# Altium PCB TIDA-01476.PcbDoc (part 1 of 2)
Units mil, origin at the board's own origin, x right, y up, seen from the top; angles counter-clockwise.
Board outline 2952.76 x 1377.95 mil, 4 copper layers (Layer 1 - Top Layer, Layer 2 - GND, Layer 3 - PWR, Layer 4 - Bottom Layer), stack 32.668 mil thick; 140 components, 50 nets, 358 pads, 357 vias.
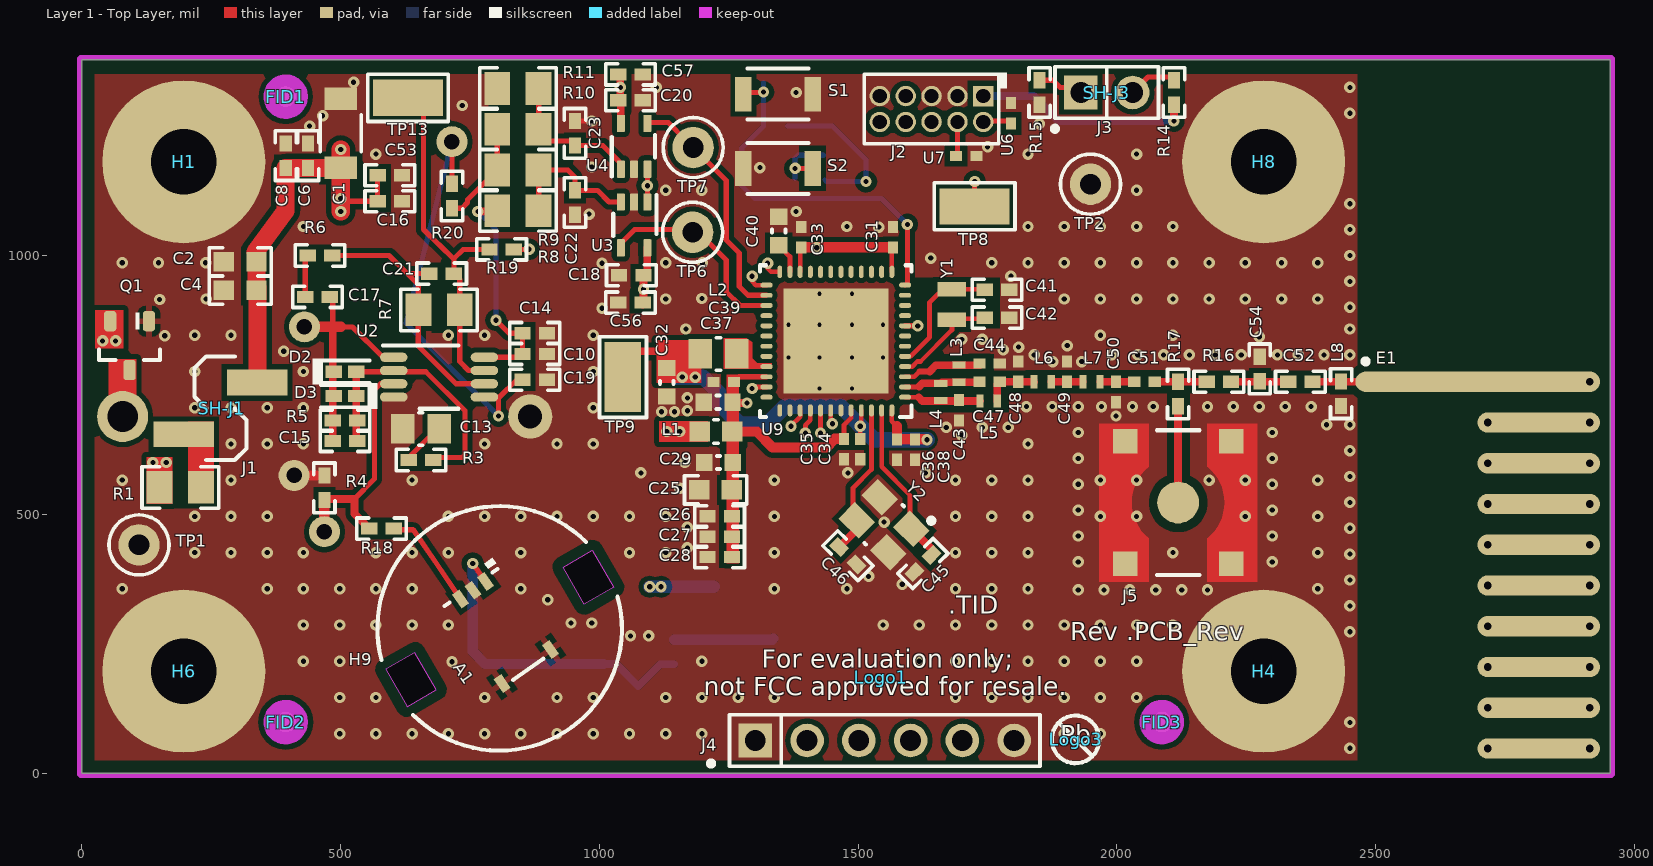
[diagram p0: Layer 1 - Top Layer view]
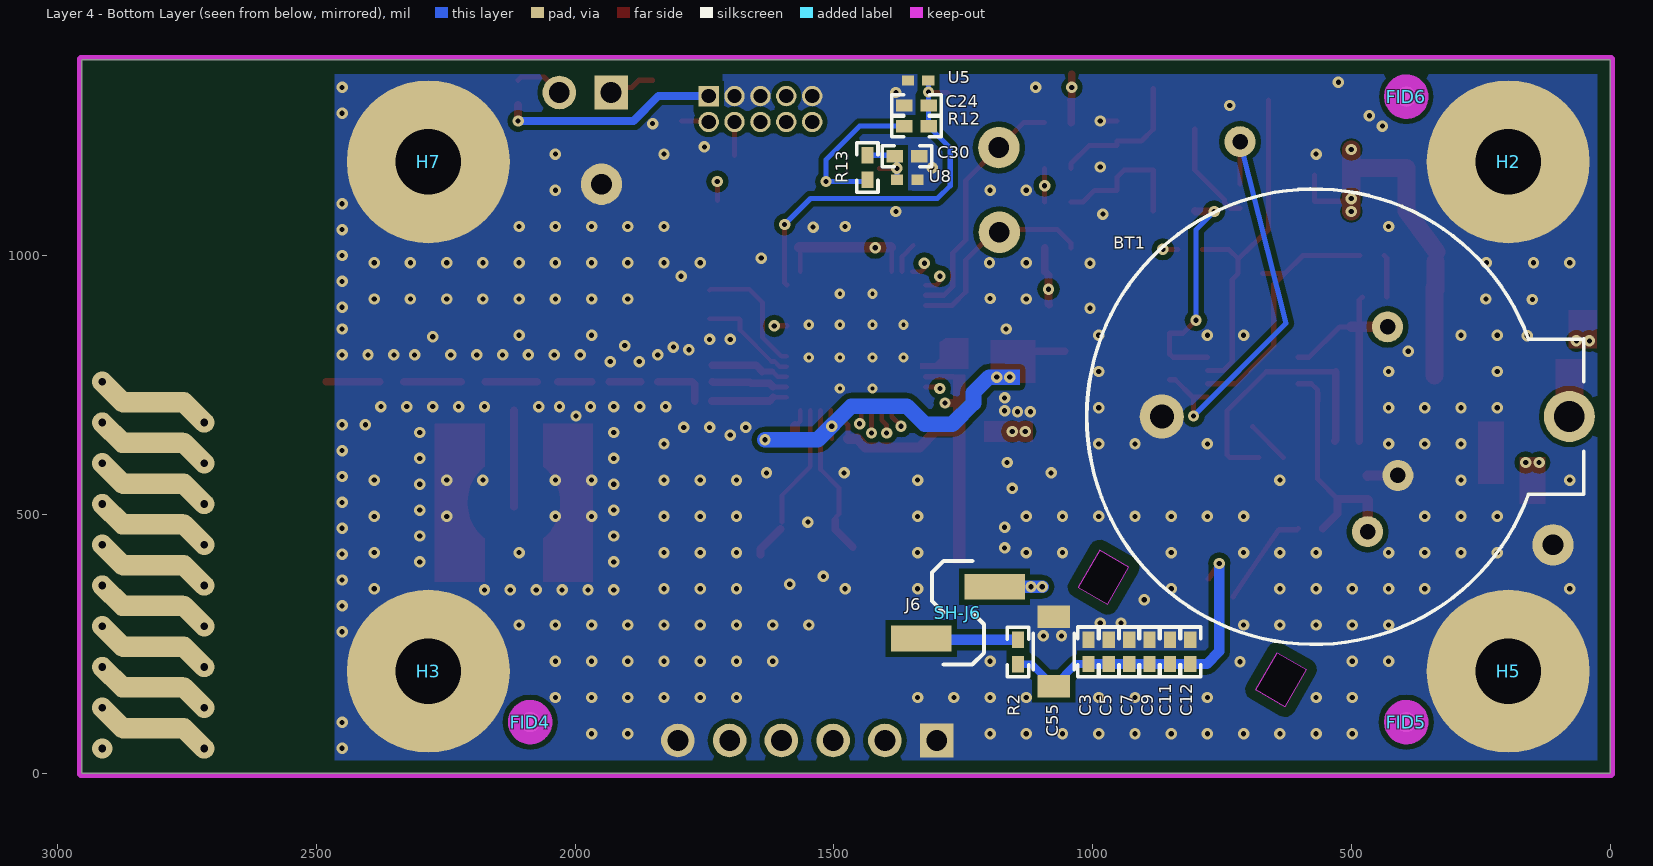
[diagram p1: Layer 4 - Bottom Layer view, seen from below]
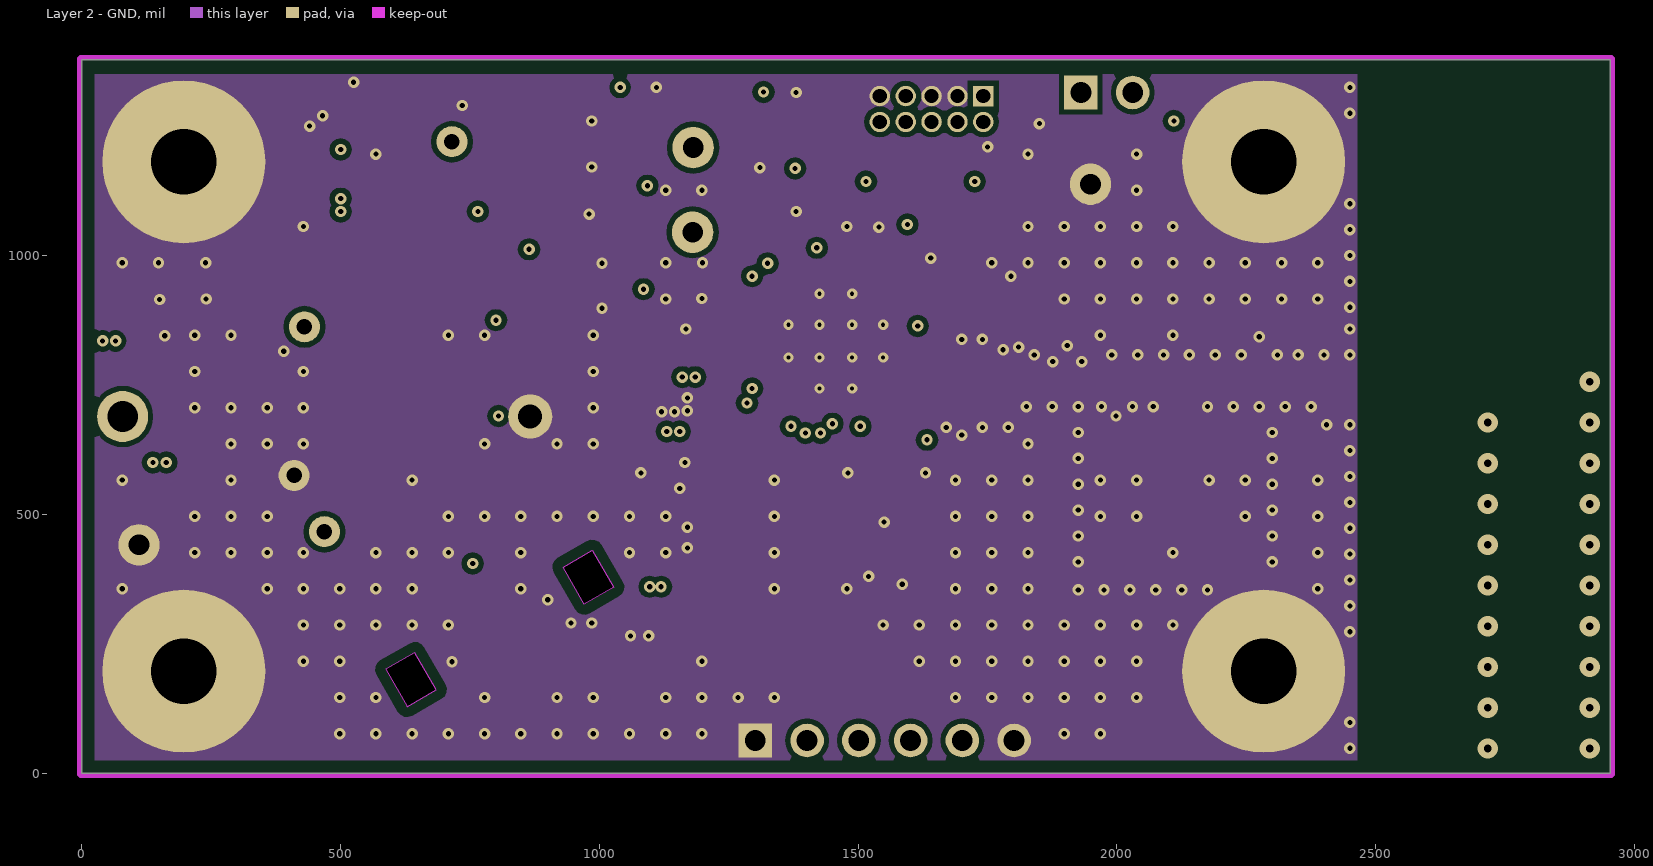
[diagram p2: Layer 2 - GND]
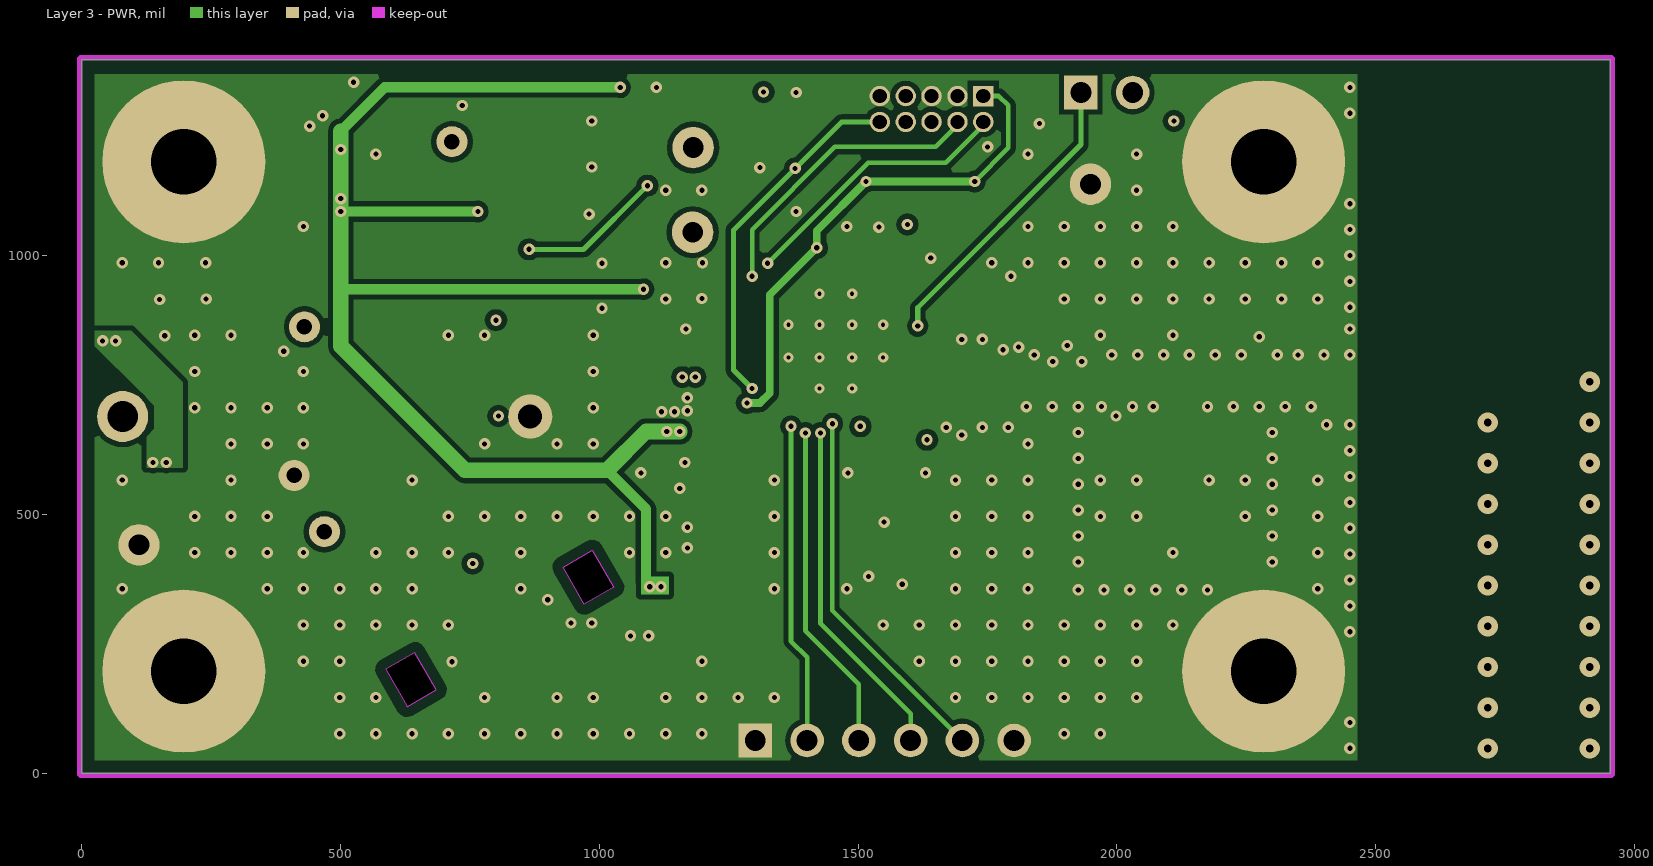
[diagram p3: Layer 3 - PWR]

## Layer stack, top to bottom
Top Solder: solder mask 0.4, Solder Resist, Dk 3.5
Layer 1 - Top Layer: signal copper 1.417
Dielectric1: core 9, 370HR, Dk 4.5
Layer 2 - GND: signal copper 1.417
Dielectric 3: prepreg 9, 370HR, Dk 4.5
Layer 3 - PWR: signal copper 1.417
Dielectric 2: core 9, 370HR, Dk 4.5
Layer 4 - Bottom Layer: signal copper 1.417
Bottom Solder: solder mask 0.4, Solder Resist, Dk 3.5

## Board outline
0,0 2952.76,0 2952.76,1377.95 0,1377.95

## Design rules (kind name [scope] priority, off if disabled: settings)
BoardOutlineClearance [All] p1: gap=20 ignorepadtopadclearanceinfootprint=FALSE
Clearance Clearance_1 [inpoly] p1: gap=10 ignorepadtopadclearanceinfootprint=FALSE except(0: Arc-Hole Track-Hole SMDPad-Hole THPad-Hole Via-Hole Fill-Hole Poly-Hole Region-Hole Text-Hole)
Clearance "Stitching GND" [IsStitchingVia and InNet('GND') vs (IsVia and (Not IsStitchingVia)) Or IsPad] p2: gap=20 ignorepadtopadclearanceinfootprint=FALSE except(0: Arc-Hole Track-Hole SMDPad-Hole THPad-Hole Via-Hole Fill-Hole Poly-Hole Region-Hole Text-Hole)
Clearance [All] p3: gap=5.91 ignorepadtopadclearanceinfootprint=FALSE except(0: Arc-Hole Track-Hole SMDPad-Hole THPad-Hole Via-Hole Fill-Hole Poly-Hole Region-Hole Text-Hole)
ComponentClearance ComponentClearance_Shunt [InComponentClass('Header') vs InComponentClass('Shunt')] p1: gap=0 collisioncheckmode=3 verticalgap=0 showdistances=FALSE
ComponentClearance ComponentClearance_H9 [incomponent('A1') vs incomponent('H9')] p2: gap=0 collisioncheckmode=3 verticalgap=0 showdistances=FALSE
ComponentClearance [All] p3: gap=3.94 collisioncheckmode=3 verticalgap=3.94 showdistances=FALSE
FabricationTestPointUsage TestPointUsage [All] p1: valid=0 allowmultiple=FALSE
FabricationTestpoint Testpoint [All] p1: side=3 testpointundercomponent=TRUE minsize=40 maxsize=100 preferedsize=60 minholesize=0 maxholesize=40 preferedholesize=32 testpointgrid=1 allowsidetop=TRUE allowsidebottom=TRUE usegrid=TRUE gridtolerance=0.01
HoleSize [All] p1: absolutevalues=TRUE maxlimit=500 minlimit=7.8 maxpercent=80.000 minpercent=20.000
MinimumAnnularRing [All] p1: minimumring=5
MinimumSolderMaskSliver [All] p1: minsoldermaskwidth=4
PolygonConnect PolygonConnect_TR [incomponent('A1') or  incomponent('Q1')] p1: connectstyle=Relief reliefconductorwidth=12 reliefentries=4 polygonreliefangle="90 Angle" airgapwidth=10
PolygonConnect [All] p2: connectstyle=Direct reliefconductorwidth=10 reliefentries=4 polygonreliefangle="90 Angle" airgapwidth=10
RoutingVias [All] p1: holewidth=10 width=22 viastyle="Through Hole" minholewidth=7.8 minwidth=19 maxholewidth=28 maxwidth=50
SilkToBoardRegionClearance [All] p1 off:
SilkToSilkClearance SilkToSilkClearance_1 [(HasFootprint('Pb-Free_Overlay_Medium') OR HasFootprint('Pb-Free_Overlay_Small')) vs (HasFootprint('Pb-Free_Overlay_Medium') OR HasFootprint('Pb-Free_Overlay_Small'))] p1: silktosilkclearance=0
SilkToSilkClearance [All] p2: silktosilkclearance=3
SilkToSolderMaskClearance SilkscreenOverComponentPads [IsPad] p1: minsilkscreentomaskgap=3 clearancetoexposedcopper=TRUE
SolderMaskExpansion [All] p1: expansion=0
Width [All] p1: maxlimit=100 minlimit=6 preferedwidth=10 minimp=50.000000 maximp=50.000000 favimp=50.000000
22 further rules are at their usual default settings.

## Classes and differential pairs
component class Shunt: SH-J1 SH-J3 SH-J6
component class AssemblyNote: ZZ1 ZZ2 ZZ3 ZZ4
component class TIDA-01476_POWER_PIR_802: A1 BT1 C1 C2 C3 C4 C5 C6 C7 C8 C9 C10 C11 C12 C13 C14 C15 C16 C17 C18 C19 C20 C21 C22 C23 C53 C55 C56 C57 D2 D3 J1 J6 Q1 R1 R2 R3 R4 R5 R6 R7 R8 R9 R10 R11 R18 R19 R20 TP1 TP2 TP6 TP7 TP13 U2 U3 U4
component class TIDA-01476_MCU: C24 C25 C26 C27 C28 C29 C30 C31 C32 C33 C34 C35 C36 C37 C38 C39 C40 C41 C42 C43 C44 C45 C46 C47 C48 C49 C50 C51 C52 C54 E1 J2 J3 J4 J5 L1 L2 L3 L4 L5 L6 L7 L8 R12 R13 R14 R15 R16 R17 S1 S2 TP8 TP9 U5 U6 U7 U8 U9 Y1 Y2
component class Header: J1 J2 J3 J4 J6
component class "Mounting Holes": H1 H4 H6 H8
component class TIDA-01476_TID_Hardware: FID1 FID2 FID3 FID4 FID5 FID6 H1 H2 H3 H4 H5 H6 H7 H8 H9 Logo1 Logo3 SH-J1 SH-J3 SH-J6 ZZ1 ZZ2 ZZ3 ZZ4
component class FiducialMark: FID1 FID2 FID3 FID4 FID5 FID6

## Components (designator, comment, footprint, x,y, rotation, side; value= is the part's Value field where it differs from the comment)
A1 "IRS-B210ST01-R1" Murata_IRS-B210ST01 807.09,279.53 r305 top value=3.6mVp-p
BT1 "BS-7" BAT_BS-7 472.44,688.98 r0 bottom locked
C1 "C3216X5R1A107M160AC" 1206_190 500,1236.22 r90 top value=100uF
C2 "C1608X5R0J106M" 0603 305.78,988.19 r180 top value=10uF
C3 "GRM155R60J106ME44D" 0402 1007.89,234.25 r90 bottom value=10uF
C4 "C1608X7R1C105K" 0603 305.78,933.07 r180 top value=1uF
C5 "C1005X5R1A105K050BB" 0402 968.52,234.25 r90 bottom value=1uF
C6 "C1005X7R1H104K050BB" 0402 437.01,1192.91 r90 top value=0.1uF
C7 "C1005X7R1H104K050BB" 0402 929.15,234.25 r90 bottom value=0.1uF
C8 "C1005X7R1C103K" 0402 393.7,1192.91 r90 top value=0.01uF
C9 "C1005X7R1C103K" 0402 889.78,234.25 r90 bottom value=0.01uF
C10 "C1005X7R1H102K" 0402 875,810 r0 top value=1000pF
C11 "C1005X7R1H102K" 0402 850.41,234.25 r90 bottom value=1000pF
C12 "C0402C101J3GACTU" 0402 811.04,234.25 r90 bottom value=100pF
C13 "C2012X5R1A336M125AC" 0805_145 655,665 r180 top value=33uF
C14 "C1005X7R1H104K" 0402 875,850 r180 top value=0.1uF
C15 "C1005X7R1E103K" 0402 508.35,641.73 r0 top value=0.01uF
C16 "C1005X7R1H104K" 0402 595,1105 r180 top value=0.1uF
C17 "C1005X5R1A335K050BC" 0402 455,920 r0 top value=3.3uF
C18 "C1005X7R1H104K" 0402 1061.54,962.03 r0 top value=0.1uF
C19 "C1005X7R1H104K" 0402 875,760 r0 top value=0.1uF
C20 "C1005X7R1H104K" 0402 1060,1300 r180 top value=0.1uF
C21 "C1005C0G1E102J" 0402 695,965 r180 top value=1000pF
C22 "C1005X7R1H104K" 0402 952.76,1102.36 r270 top value=0.1uF
C23 "C1005X7R1H104K" 0402 952.76,1236.22 r90 top value=0.1uF
C24 "C1005X7R1H222K" 0402 1340,1290 r180 bottom value=2200pF
C25 "C1608X7R1C105K" 0603 1224.41,547.24 r180 top value=1uF
C26 "C1005X7R1C103K" 0402 1232.28,496.06 r180 top value=0.01uF
C27 "C1005X7R1H102K" 0402 1232.28,456.69 r180 top value=1000pF
C28 "C0402C101J3GACTU" 0402 1232.28,417.32 r180 top value=100pF
C29 "C1608X5R0J226M080AC" 0603L 1230.16,600.14 r180 top value=22uF
C30 "C1005X7R1H222K" 0402 1358.37,1191.9 r0 bottom value=2200pF
C31 "GRM155R70J104KA01D" 0402L 1566.93,1035.43 r90 top value=0.1uF
C32 "C1608X5R0J226M080AC" 0603L 1130,755 r270 top value=22uF
C33 "GRM155R70J104KA01D" 0402L 1389.76,1035.43 r90 top value=0.1uF
C34 "GRM155R70J104KA01D" 0402L 1503.94,625.98 r270 top value=0.1uF
C35 "GRM155R70J104KA01D" 0402L 1472.44,625.98 r270 top value=0.1uF
C36 "GRM155R70J104KA01D" 0402L 1575,625 r270 top value=0.1uF
C37 "C1608X5R0J226M080AC" 0603L 1229.33,716.54 r180 top value=22uF
C38 "GRM155R70J104KA01D" 0402L 1610,625 r270 top value=0.1uF
C39 "GRM155R70J104KA01D" 0402L 1240.16,755.91 r180 top value=0.1uF
C40 "GRM188R70J105KA01D" 0603L 1346.46,1047.24 r270 top value=1uF
C41 "GRM1555C1E120JA01D" 0402 1768,934 r180 top value=12pF
C42 "GRM1555C1E120JA01D" 0402 1768,880 r180 top value=12pF
C43 "GRM1555C1H3R6CA01D" 0402L 1694.88,700.91 r90 top value=3.6pF
C44 "GRM1555C1H101JA01D" 0402L 1753.94,791.46 r0 top value=100pF
C45 "GRM1555C1E120JA01D" 0402 1625,405 r225 top value=12pF
C46 "GRM1555C1E120JA01D" 0402 1480,420 r315 top value=12pF
C47 "GRM1555C1H3R6CA01D" 0402L 1753.94,756.03 r180 top value=3.6pF
C48 "GRM1555C1H2R7CA01D" 0402L 1809.06,775.72 r90 top value=2.7pF
C49 "GRM1555C1H6R2CA01D" 0402L 1903.54,775.72 r90 top value=6.2pF
C50 "GRM1555C1H3R3CA01D" 0402L 1998.03,736.35 r270 top value=3.3pF
C51 "GRM1555C1H101JA01D" 0402L 2053.15,756.03 r180 top value=100pF
C52 "GJM1555C1HR60BB01D" 0402 2354.33,756.03 r0 top value=0.6pF
C53 "C1005X7R1H102K" 0402 595,1155 r0 top value=1000pF
C54 "GRM1555C1H1R0CA01D" 0402 2276,781 r90 top value=1pF
C55 "C3216X5R1A107M160AC" 1206_190 1075,235 r90 bottom value=100uF
C56 "C1005X7R1H102K" 0402 1060,909 r180 top value=1000pF
C57 "C1005X7R1H102K" 0402 1060,1350 r0 top value=1000pF
D2 "1N4148X-TP" SOD-523 508.35,775.59 r0 top value=75V
D3 "1N4148X-TP" SOD-523 508.35,728.35 r180 top value=75V
E1 "ANTENNA_HELICAL" ANTENNA_HELICAL 2480.32,756.03 r270 top locked net-tie
FID1 "Fiducial" Fiducial10-20 393.7,1307.09 r0 top
FID2 "Fiducial" Fiducial10-20 393.7,98.43 r0 top
FID3 "Fiducial" Fiducial10-20 2086.61,98.43 r0 top
FID4 "Fiducial" Fiducial10-20 2086.61,98.43 r90 bottom
FID5 "Fiducial" Fiducial10-20 393.7,98.43 r90 bottom
FID6 "Fiducial" Fiducial10-20 393.7,1307.09 r90 bottom
H1 "NY PMS 440 0025 PH" "NY PMS 440 0025 PH" 196.85,1181.1 r0 top locked
H2 "1902C" Keystone_1902C 196.85,1181.1 r180 bottom locked
H3 "1902C" Keystone_1902C 2283.46,196.85 r180 bottom locked
H4 "NY PMS 440 0025 PH" "NY PMS 440 0025 PH" 2283.46,196.85 r0 top locked
H5 "1902C" Keystone_1902C 196.85,196.85 r180 bottom locked
H6 "NY PMS 440 0025 PH" "NY PMS 440 0025 PH" 196.85,196.85 r0 top locked
H7 "1902C" Keystone_1902C 2283.46,1181.1 r180 bottom locked
H8 "NY PMS 440 0025 PH" "NY PMS 440 0025 PH" 2283.46,1181.1 r0 top locked
H9 "IML-0669" Murata_IML-0669 807.09,279.53 r210 top
J1 "87898-0204" Molex_87898-0204 267.72,704.72 r90 top
J2 "GRPB052VWVN-RC" CONN_GRPB052VWVN-RC 1641.73,1283.15 r180 top
J3 "TSW-102-07-G-S" TSW-102-07-G-S 1980.32,1314.96 r0 top
J4 "TSW-106-07-G-S" TSW-106-07-G-S 1551.18,62.99 r0 top
J5 "CONSMA001-SMD-G" Linx_CONSMA001-SMD-G 2118.11,522.68 r0 top
J6 "87898-0204" Molex_87898-0204 1260,310 r90 bottom
L1 "BLM18HE152SN1D" 0603_095 1225,660 r180 top value="1500 ohm"
L2 "MLZ2012N6R8LT000" 0805_145 1230,810 r180 top value=6.8uH
L3 "LQW15AN7N5G00D" LQW15A_00_10 1694.88,771.78 r270 top value=7.5nH
L4 "LQW15AN18NJ00D" LQW15A_00_10 1659.45,736.35 r90 top value=18nH
L5 "LQW15AN7N5G00D" LQW15A_00_10 1752,719 r0 top value=7.5nH
L6 "LQW15AN6N8G00D" LQW15A_00_10 1856.3,756.03 r0 top value=6.8nH
L7 "LQW15AN6N8G00D" LQW15A_00_10 1950.79,756.03 r0 top value=6.8nH
L8 "LQW15AN11NG00D" 0402 2433,733 r270 top value=11nH
Logo1 "FCC disclaimer" FCC_disclaimer_stacked 1543.31,185.04 r0 top
Logo3 "Pb-Free Symbol" Pb-Free_Overlay_Small 1920,65 r0 top
Q1 "SI2323DS" SOT-23 92,826 r270 top value=-20V
R1 "CRCW08050000Z0EA" 0805_HV 190,552 r0 top value=0
R2 "CRCW0402619KFKED" 0402 1144,234 r90 bottom value=619k
R3 "CRCW04026K81FKED" 0402 655,605 r0 top value=6.81k
R4 "CRCW04021M30FKED" 0402 468.5,551.18 r270 top value=1.30Meg
R5 "CRCW04021M50FKED" 0402 508.35,681.1 r180 top value=1.50Meg
R6 "CRCW040268K1FKED" 0402 460,1000 r0 top value=68.1k
R7 "RMCF0805JT15M0" 0805_HV 690,895 r0 top value=15Meg
R8 "RMCF0805JT15M0" 0805_HV 842.52,1086.61 r180 top value=15Meg
R9 "RMCF0805JT15M0" 0805_HV 842.52,1165.35 r0 top value=15Meg
R10 "RMCF0805JT15M0" 0805_HV 842.52,1244.09 r180 top value=15Meg
R11 "RMCF0805JT15M0" 0805_HV 842.52,1322.83 r0 top value=15Meg
R12 "CRCW040247K5FKED" 0402 1340,1250 r0 bottom value=47.5k
R13 "CRCW040247K5FKED" 0402 1435,1170 r270 bottom value=47.5k
R14 "CRCW04020000Z0ED" 0402 2110.24,1314.96 r270 top value=0
R15 "CRCW0402100KFKED" 0402 1850.39,1314.96 r90 top value=100k
R16 "CRCW04020000Z0ED" 0402 2196.85,756.03 r0 top value=0
R17 "CRCW04020000Z0ED" 0402 2118.11,732.41 r270 top value=0
R18 "CRCW04020000Z0ED" 0402 578.74,472.44 r180 top value=0
R19 "CRCW04020000Z0ED" 0402 811.02,1011.81 r0 top value=0
R20 "CRCW04020000Z0ED" 0402 715,1115 r270 top value=0
S1 "B3U-1000P" SW_B3U-1000P 1345,1312 r180 top
S2 "B3U-1000P" SW_B3U-1000P 1345,1168.26 r0 top
SH-J1 "969102-0000-DA" SNT-100-BK-G#1 270,705 r90 top value=1x2
SH-J3 "969102-0000-DA" SNT-100-BK-G#1 1980.32,1314.96 r0 top value=1x2
SH-J6 "969102-0000-DA" SNT-100-BK-G#2 1260,310 r90 bottom value=1x2
TP1 "5001" Keystone5001 110.24,440.94 r0 top value=Black
TP2 "5001" Keystone5001 1948.82,1137.8 r0 top value=Black
TP6 "5004" Keystone5004 1180,1045 r0 top value=Yellow
TP7 "5004" Keystone5004 1181.1,1208.66 r0 top value=Yellow
TP8 "5015" Testpoint_Keystone_Miniature 1725,1095 r180 top value=SMT
TP9 "5015" Testpoint_Keystone_Miniature 1045,765 r90 top value=SMT
TP13 "5015" Testpoint_Keystone_Miniature 630,1305 r0 top value=SMT
U2 "LPV802DGKR" DGK0008A_N 690,765 r0 top
U3 "TLV3691IDCK" DCK0005A_N 1066.93,1059.06 r270 top
U4 "TLV3691IDCK" DCK0005A_N 1067,1211 r90 top
U5 "TPD1E10B06DPYR" DPY0002A 1337,1338 r0 bottom
U6 "TPD1E10B06DPYR" DPY0002A 1795,1275 r90 top
U7 "TPD1E10B06DPYR" DPY0002A 1708.66,1192.6 r0 top
U8 "TPD1E10B06DPYR" DPY0002A 1358.09,1146.3 r180 bottom
U9 "CC1310F128RGZR" RGZ0048A 1456.69,834.65 r180 top
Y1 "FC-12M 32.7680KA-A3" Epson_FC-12M 1681.1,905.51 r90 top
Y2 "TSX-3225 24.0000MF20G-AC3" EPSON_TSX-3225 1550,480 r225 top
ZZ1 "These assemblies are ESD sensitive, ESD precautions shall be observed." AssemblyNote 160,1950 r0 top
ZZ2 "These assemblies must be clean and free from flux and all contaminants. Use of no clean flux is not acceptable." AssemblyNote 160,1820 r0 top
ZZ3 "These assemblies must comply with workmanship standards IPC-A-610 Class 2, unless otherwise specified." AssemblyNote 160,1695 r0 top
ZZ4 "After verifying lens of A1 is clean and undistorted, snap cover H9 over sensor A1 during final hardware assembly." AssemblyNote 160,1575 r0 top

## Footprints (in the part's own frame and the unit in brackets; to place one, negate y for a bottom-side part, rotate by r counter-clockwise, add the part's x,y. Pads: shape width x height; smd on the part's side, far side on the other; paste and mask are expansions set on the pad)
0402 [mm] "0402 from SM-752 data"
  rect 0.8x0.6 smd: 1(-0.6,0) 2(0.6,0)
  silkscreen extent -1.22,-0.52 1.22,0.52, body extent -0.55,-0.3 0.55,0.3, height 0.6
0402L [mm] "0402 from SM-752 data"
  rect 0.6x0.5 smd: 1(-0.5,0) 2(0.5,0)
  body extent -0.55,-0.3 0.55,0.3, height 0.6
0603 [mm] "0603 from SM-752 data"
  rect 1x0.95 smd: 1(-0.8,0) 2(0.8,0)
  silkscreen extent -1.52,-0.69 1.52,0.69, body extent -0.87,-0.47 0.87,0.47, height 0.85
0603_095 [mm] "0603_095"
  rect 1x1 smd: 1(-0.8,0) 2(0.8,0)
  silkscreen extent -0.1,-0.58 0.1,0.58, body extent -0.87,-0.48 0.87,0.48, height 0.95
0603L [mm] "0603 from SM-752 data"
  rect 0.8x0.85 smd: 1(-0.7,0) 2(0.7,0)
  silkscreen extent -0.07,-0.33 0.07,0.33, body extent -0.87,-0.47 0.87,0.47, height 0.85
0805_145 [mm] "0805 / 1.45mm height"
  rect 1.15x1.45 smd: 1(-0.9,0) 2(0.9,0)
  silkscreen extent -0.1,-0.8 0.1,0.8, body extent -1.1,-0.72 1.1,0.72, height 1.45
0805_HV [mil] "0805 with 30mil clearance between pads"
  rect 50x63 smd: 1(-40,0) 2(40,0)
  silkscreen extent -74,-40 74,40, body extent -43,-29 43,29, height 57
1206_190 [mm] "1206_190"
  rect 1.1x1.6 smd: 1(-1.7,0) 2(1.7,0)
  silkscreen extent -0.9,-1 0.9,1, body extent -1.75,-0.95 1.75,0.95, height 1.9
ANTENNA_HELICAL [mm] "SMD, 1-Lead"
  round 1 smd paste-1 mask-1: 1(0,0)
  oval 1x12 smd paste-12 mask-12: ""(0,5.5)
  oval 1x2.414 smd far side rot 45 paste-1.5 mask-1.5: ""(0.5,10.5) ""(1.5,6.5) ""(2.5,10.5) ""(3.5,6.5) ""(4.5,10.5) ""(5.5,6.5) ""(6.5,10.5) ""(7.5,6.5) ""(8.5,10.5) ""(9.5,6.5) ""(10.5,10.5) ""(11.5,6.5) ""(12.5,10.5) ""(13.5,6.5) ""(14.5,10.5) ""(15.5,6.5) ""(16.5,10.5) ""(17.5,6.5)
  oval 1x4 smd far side paste-4 mask-4: ""(1,8.5) ""(3,8.5) ""(5,8.5) ""(7,8.5) ""(9,8.5) ""(11,8.5) ""(13,8.5) ""(15,8.5) ""(17,8.5)
  oval 1x6 smd paste-6 mask-6: ""(2,8.5) ""(4,8.5) ""(6,8.5) ""(8,8.5) ""(10,8.5) ""(12,8.5) ""(14,8.5) ""(16,8.5) ""(18,8.5)
  silkscreen extent -1.12,-0.12 -0.88,0.13
AssemblyNote [mil] "Assembly Note"
BAT_BS-7 [mm] "Memory Protection Devices CR2032 battery holder"
  round 2.5 hole 1.5: 1(-10,0)
  round 2.17 hole 1.181: 2(10,0)
  silkscreen extent -10.7,-11.16 13.68,11.18, body extent -10.69,-11.16 13.7,11.16, height 9.02
CONN_GRPB052VWVN-RC [mm] "SULLINS"
  rect 1x1 hole 0.7 mask+0.08: 1(-2.54,-0.635)
  round 1 hole 0.7 mask+0.08: 2(-2.54,0.635) 3(-1.27,-0.635) 4(-1.27,0.635) 5(0,-0.635) 6(0,0.635) 7(1.27,-0.635) 8(1.27,0.635) 9(2.54,-0.635) 10(2.54,0.635)
  silkscreen extent -3.7,-1.8 3.3,1.7, body extent -3.17,-1.7 3.17,1.7, height 4
DCK0005A_N [mm] "SOT353, 5-Leads, Body 2x1.3mm, Pitch 0.65mm, Lead Span 2.1mm, IPC Medium Density"
  rrect25% 0.85x0.4 smd: 1(-1.125,0.65) 2(-1.125,0) 3(-1.125,-0.65) 4(1.125,-0.65) 5(1.125,0.65)
  silkscreen extent -1.48,-1.02 0.55,1.1, body extent -1.14,-1 1.14,1, height 0.95
DGK0008A_N [mm] "TSOP, 8-Leads, Body 3x3mm, Pitch 0.65mm, IPC Medium Density"
  oval 1.35x0.45 smd: 1(-2.225,0.975) 2(-2.225,0.325) 3(-2.225,-0.325) 4(-2.225,-0.975) 5(2.225,-0.975) 6(2.225,-0.325) 7(2.225,0.325) 8(2.225,0.975)
  silkscreen extent -2.75,-1.55 0.95,1.55, body extent -2.45,-1.5 2.45,1.5, height 0.96
DPY0002A [mm] "R-PX2SON-N2"
  rect 0.6x0.5 smd: 1(-0.5,0) 2(0.5,0)
  body extent -0.55,-0.35 0.55,0.35, height 0.4
Epson_FC-12M [mm] "Epson"
  rect 0.7x1.4 smd: 1(-0.75,0) 2(0.75,0)
  body extent -1.05,-0.63 1.05,0.63, height 0.6
EPSON_TSX-3225 [mm] "SMD, 4-Leads, Body 2.65x3.35mm, Height 0.6mm"
  rect 1.15x1.4 smd: 1(-0.8,1.1) 2(-0.8,-1.1) 3(0.8,-1.1) 4(0.8,1.1)
  silkscreen extent -1.9,-0.05 1.33,1.62, body extent -1.33,-1.68 1.33,1.68, height 0.61
FCC_disclaimer_stacked [mil]
Fiducial10-20 [mm]
  round 1 smd mask+0.5: 1(0,0)
  Layer 1 - Top Layer keep-out circle w1.178: c0,0 r0.5
Keystone5001 [mil] "For Keystone 500x miniature loop terminals"
  round 80 hole 40: 1(0,0)
  silkscreen extent -58,-58 58,58, body extent -49,-49 49,49, height 182
Keystone5004 [mil] "For Keystone 500x miniature loop terminals"
  round 80 hole 40: 1(0,0)
  silkscreen extent -58,-58 58,58, body extent -49,-49 49,49, height 182
Keystone_1902C [mil] "Hex Standoff, 4-40 threaded, nylon"
  body extent -145,-126 146,126, height 501
Linx_CONSMA001-SMD-G [mm] "SMD, 5-Leads, Body 7x7mm, Height 10.5mm"
  round 2.05 smd: 1(0,0)
  rect 1.2x1.2 smd: 2(-2.6,-3) 3(2.6,-3) 4(2.6,3) 5(-2.6,3)
  Layer 1 - Top Layer region: 3.88,-3.88 1.44,-3.88 1.44,-1.761 1.448,-1.761 2.062,-0.974 2.28,0 2.062,0.974 1.448,1.761 1.448,1.761 1.44,1.761 1.44,3.88 3.88,3.88
  Layer 1 - Top Layer region: -3.88,-3.88 -1.44,-3.88 -1.44,-1.761 -1.448,-1.761 -2.062,-0.974 -2.28,0 -2.062,0.974 -1.448,1.761 -1.448,1.761 -1.44,1.761 -1.44,3.88 -3.88,3.88
  silkscreen extent -1.04,-3.55 1.04,3.55, body extent -3.55,-3.55 3.55,3.55, height 10.5
LQW15A_00_10 [mm] "Murata"
  rect 0.35x0.65 smd: 1(-0.425,0) 2(0.425,0)
  body extent -0.55,-0.35 0.55,0.35, height 0.6
Molex_87898-0204 [mm] "Header, 2.54 mm, 2x1, R/A, SMT"
  rect 1.27x2.96 smd: 1(-1.27,1.8) 2(1.27,-1.8)
  silkscreen extent -2.54,-1.27 2.54,1.27, body extent -2.54,-2.4 2.54,2.4, height 9.65
Murata_IML-0669 [mil] "Pyroelectric Infrared Lens, TH"
  Keep-Out Layer board cut-out: 165.35,-41.34 230.31,-41.34 230.32,41.34 165.35,41.34
  Keep-Out Layer board cut-out: -230.31,41.34 -165.35,41.34 -165.35,-41.34 -230.31,-41.34
  silkscreen extent -228,-236 228,236, body extent -256,-236 256,236, height 335
Murata_IRS-B210ST01 [mm] "SMD, 5-Leads, Body 4.7x4.7mm"
  rect 0.825x0.45 smd: 1(-2.288,0.75) 2(-2.288,0) 3(-2.288,-0.75) 4(2.288,-1.45) 5(2.288,1.45)
  silkscreen extent -3.05,-1.6 2.45,1.7, body extent -2.45,-2.45 2.45,2.45, height 2.61
"NY PMS 440 0025 PH" [mm] "4-40 nylon screw and mounting hole"
  round 8 hole 3.2: 1(0,0)
  body extent -3.3,-3.3 3.3,3.3, height 2.69
Pb-Free_Overlay_Small [mil]
  silkscreen extent -46,-46 46,46
RGZ0048A [mm] "QFN, 48-Leads, Body 7x7mm, Pitch 0.5mm, Thermal Pad 5.15X5.15mm, TI recommended"
  oval 0.6x0.24 smd: 1(-3.4,2.75) 2(-3.4,2.25) 3(-3.4,1.75) 4(-3.4,1.25) 5(-3.4,0.75) 6(-3.4,0.25) 7(-3.4,-0.25) 8(-3.4,-0.75) 9(-3.4,-1.25) 10(-3.4,-1.75) 11(-3.4,-2.25) 12(-3.4,-2.75) 25(3.4,-2.75) 26(3.4,-2.25) 27(3.4,-1.75) 28(3.4,-1.25) 29(3.4,-0.75) 30(3.4,-0.25) 31(3.4,0.25) 32(3.4,0.75) 33(3.4,1.25) 34(3.4,1.75) 35(3.4,2.25) 36(3.4,2.75)
  oval 0.24x0.6 smd: 13(-2.75,-3.4) 14(-2.25,-3.4) 15(-1.75,-3.4) 16(-1.25,-3.4) 17(-0.75,-3.4) 18(-0.25,-3.4) 19(0.25,-3.4) 20(0.75,-3.4) 21(1.25,-3.4) 22(1.75,-3.4) 23(2.25,-3.4) 24(2.75,-3.4) 37(2.75,3.4) 38(2.25,3.4) 39(1.75,3.4) 40(1.25,3.4) 41(0.75,3.4) 42(0.25,3.4) 43(-0.25,3.4) 44(-0.75,3.4) 45(-1.25,3.4) 46(-1.75,3.4) 47(-2.25,3.4) 48(-2.75,3.4)
  rect 5.15x5.15 smd paste-2.6: 49(0,0)
  silkscreen extent -3.72,-3.72 3.72,3.72, body extent -3.58,-3.57 3.57,3.58, height 1.01
SNT-100-BK-G#1 [mil] "Samtec STEP model"
  round 1 on Mech3: 0(0,0)
  body extent -100,-50 100,50, height 344
SNT-100-BK-G#2 [mil] "Samtec STEP model"
  round 1 on Mech4: 0(0,0)
  body extent -100,-50 100,50, height 344
SOD-523 [mm] "NXP Semiconductor recommended land pattern, nominal STEP model"
  rect 0.8x0.6 smd paste-0.05: 1(-0.55,0) 2(0.55,0)
  silkscreen extent -1.6,-0.64 1.2,0.63, body extent -0.8,-0.4 0.8,0.4, height 0.72
SOT-23 [mm] "SOT23, 3-Leads, Body 2.9x1.3mm, Pitch 0.95mm, Lead Span 2.5mm, IPC Medium Density"
  rrect50% 1x0.6 smd: 1(-1.2,0.95) 2(-1.2,-0.95) 3(1.2,0)
  silkscreen extent -1.63,-1.5 0.7,1.5, body extent -1.16,-1.45 1.21,1.45, height 1
SW_B3U-1000P [mm] "OMRON"
  rect 0.8x1.7 smd: 1(-1.7,0) 2(1.7,0)
  silkscreen extent -1.5,-1.25 1.5,1.25, body extent -1.5,-1.25 1.5,1.25, height 1.75
Testpoint_Keystone_Miniature [mil] "Miniature SMT test point"
  rect 135x70 smd: 1(0,0)
  silkscreen extent -78,-46 78,45, body extent -52,-20 52,20, height 61
TSW-102-07-G-S [mm] "Samtec 100mil, 1x2, 230 mil above insulator"
  rect 1.65x1.65 hole 1.016 mask+0: 1(-1.27,0)
  round 1.65 hole 1.016 mask+0: 2(1.27,0)
  silkscreen extent -2.67,-1.9 2.54,1.27, body extent -2.54,-1.27 2.54,1.27, height 8.38
TSW-106-07-G-S [mm] "Samtec 100mil, 1x6, 230 mil above insulator"
  rect 1.65x1.65 hole 1.016 mask+0: 1(-6.35,0)
  round 1.65 hole 1.016 mask+0: 2(-3.81,0) 3(-1.27,0) 4(1.27,0) 5(3.81,0) 6(6.35,0)
  silkscreen extent -8.64,-1.27 7.62,1.27, body extent -7.62,-1.27 7.62,1.27, height 8.38

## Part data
A1: "Pyroelectric Infrared Sensors for Reflow Soldering, 3.6mVp-p, SMD", Manufacturer=MuRata, Supplier Part Number 1=IRS-B210ST01-R1-ND
BT1: "Battery Holder, CR2032, Retainer clip, TH", Manufacturer="Memory Protection Devices", Supplier Part Number 1=BS-7-ND
C1 C55: "CAP, CERM, 100 µF, 10 V, +/- 20%, X5R, 1206_190", Cap_Case=1206, Manufacturer=TDK, Supplier Part Number 1=445-6007-1-ND, TempCo=X5R, Tolerance_%=20, Value1=Unknown, Value2=10V, ValueDisplayed=100µF
C2: "CAP, CERM, 10 µF, 6.3 V, +/- 20%, X5R, 0603", Cap_Case=0603, Manufacturer=TDK, Supplier Part Number 1=445-4112-1-ND, TempCo=X5R, Tolerance_%=20, Value1="0.005 ohm", Value2=6.3V, ValueDisplayed=10µF
C3: "CAP, CERM, 10 µF, 6.3 V, +/- 20%, X5R, 0402", Cap_Case=0402, Manufacturer=MuRata, Supplier Part Number 1=81-GRM155R60J106ME4D, TempCo=X5R, Tolerance_%=20, Value1=Unknown, Value2=6.3V, ValueDisplayed=10µF
C4 C25: "CAP, CERM, 1 µF, 16 V, +/- 10%, X7R, 0603", Cap_Case=0603, Manufacturer=TDK, Supplier Part Number 1=445-1604-1-ND, TempCo=X7R, Tolerance_%=10, Value1="0.0057 ohm", Value2=16V, ValueDisplayed=1µF
C5: "CAP, CERM, 1 µF, 10 V, +/- 10%, X5R, 0402", Cap_Case=0402, Manufacturer=TDK, Supplier Part Number 1=445-4114-1-ND, TempCo=X5R, Tolerance_%=10, Value1=Unknown, Value2=10V, ValueDisplayed=1µF
C6 C7 C14 C16 C18 C19 C20 C22 C23: "CAP, CERM, 0.1 µF, 50 V, +/- 10%, X7R, 0402", Cap_Case=0402, Manufacturer=TDK, Supplier Part Number 1=445-5932-1-ND, TempCo=X7R, Tolerance_%=10, Value1=Unknown, Value2=50V, ValueDisplayed=0.1µF
C8 C9 C26: "CAP, CERM, 0.01 µF, 16 V, +/- 10%, X7R, 0402", Cap_Case=0402, Manufacturer=TDK, Supplier Part Number 1=445-1262-1-ND, TempCo=X7R, Tolerance_%=10, Value1="0.0623 ohm", Value2=16V, ValueDisplayed=0.01µF
C10 C11 C27 C53 C56 C57: "CAP, CERM, 1000 pF, 50 V, +/- 10%, X7R, 0402", Cap_Case=0402, Manufacturer=TDK, Supplier Part Number 1=445-1256-1-ND, TempCo=X7R, Tolerance_%=10, Value1="0.2381 ohm", Value2=50V, ValueDisplayed=1000pF
C12 C28: "CAP, CERM, 100 pF, 25 V, +/- 5%, C0G/NP0, 0402", Cap_Case=0402, Manufacturer=Kemet, Supplier Part Number 1=399-1022-1-ND, TempCo=C0G/NP0, Tolerance_%=5, Value1=Unknown, Value2=25V, ValueDisplayed=100pF
C13: "CAP, CERM, 33 µF, 10 V, +/- 20%, X5R, 0805", Cap_Case=0805, Manufacturer=TDK, Supplier Part Number 1=445-8238-1-ND, TempCo=X5R, Tolerance_%=20, Value1=Unknown, Value2=10V, ValueDisplayed=33µF
C15: "CAP, CERM, 0.01 µF, 25 V, +/- 10%, X7R, 0402", Cap_Case=0402, Manufacturer=TDK, Supplier Part Number 1=445-1260-1-ND, TempCo=X7R, Tolerance_%=10, Value1="0.0623 ohm", Value2=25V, ValueDisplayed=0.01µF
C17: "CAP, CERM, 3.3 µF, 10 V, +/- 10%, X5R, 0402", Cap_Case=0402, Manufacturer=TDK, Supplier Part Number 1=445-13819-1-ND, TempCo=X5R, Tolerance_%=10, Value1=Unknown, Value2=10V, ValueDisplayed=3.3µF
C21: "CAP, CERM, 1000 pF, 25 V, +/- 5%, C0G/NP0, 0402", Cap_Case=0402, Manufacturer=TDK, Supplier Part Number 1=445-2651-1-ND, TempCo=C0G/NP0, Tolerance_%=5, Value1=Unknown, Value2=25V, ValueDisplayed=1000pF
C24 C30: "CAP, CERM, 2200 pF, 50 V, +/- 10%, X7R, 0402", Cap_Case=0402, Manufacturer=TDK, Supplier Part Number 1=445-1257-1-ND, TempCo=X7R, Tolerance_%=10, Value1="0.1433 ohm", Value2=50V, ValueDisplayed=2200pF
C29 C32 C37: "CAP, CERM, 22 µF, 6.3 V, +/- 20%, X5R, 0603", Cap_Case=0603, Manufacturer=TDK, Supplier Part Number 1=445-8028-1-ND, TempCo=X5R, Tolerance_%=20, Value1=Unknown, Value2=6.3V, ValueDisplayed=22µF
C31 C33 C34 C35 C36 C38 C39: "CAP, CERM, 0.1 µF, 6.3 V, +/- 10%, X7R, 0402", Cap_Case=0402, Manufacturer=MuRata, Supplier Part Number 1=GRM155R70J104KA01D-ND, TempCo=X7R, Tolerance_%=10, Value1=Unknown, Value2=6.3V, ValueDisplayed=0.1µF
C40: "CAP, CERM, 1 µF, 6.3 V, +/- 10%, X7R, 0603", Cap_Case=0603, Manufacturer=MuRata, Supplier Part Number 1=490-3898-1-ND, TempCo=X7R, Tolerance_%=10, Value1=Unknown, Value2=6.3V, ValueDisplayed=1µF
C41 C42 C45 C46: "CAP, CERM, 12 pF, 25 V, +/- 5%, C0G/NP0, 0402", Cap_Case=0402, Manufacturer=MuRata, Supplier Part Number 1=81-GRM1555C1E120JA1D, TempCo=C0G/NP0, Tolerance_%=5, Value1=Unknown, Value2=25V, ValueDisplayed=12pF
C43 C47: "CAP, CERM, 3.6 pF, 50 V, +/- 5%, C0G/NP0, 0402", Cap_Case=0402, Manufacturer=MuRata, Supplier Part Number 1=81-GRM1555C1H3R6CA1D, TempCo=C0G/NP0, Tolerance_%=5, Value1=Unknown, Value2=50V, ValueDisplayed=3.6pF
C44 C51: "CAP, CERM, 100 pF, 50 V, +/- 5%, C0G/NP0, 0402", Cap_Case=0402, Manufacturer=MuRata, Supplier Part Number 1=81-GRM1555C1H101JA1D, TempCo=C0G/NP0, Tolerance_%=5, Value1=Unknown, Value2=50V, ValueDisplayed=100pF
C48: "CAP, CERM, 2.7 pF, 50 V, +/- 5%, C0G/NP0, 0402", Cap_Case=0402, Manufacturer=MuRata, Supplier Part Number 1=81-GRM1555C1H2R7CA1D, TempCo=C0G/NP0, Tolerance_%=5, Value1=Unknown, Value2=50V, ValueDisplayed=2.7pF
C49: "CAP, CERM, 6.2 pF, 50 V, +/- 5%, C0G/NP0, 0402", Cap_Case=0402, Manufacturer=MuRata, Supplier Part Number 1=81-GRM1555C1H6R2CA1D, TempCo=C0G/NP0, Tolerance_%=5, Value1=Unknown, Value2=50V, ValueDisplayed=6.2pF
C50: "CAP, CERM, 3.3 pF, 50 V, +/- 5%, C0G/NP0, 0402", Cap_Case=0402, Manufacturer=MuRata, Supplier Part Number 1=81-GRM1555C1H3R3CA1D, TempCo=C0G/NP0, Tolerance_%=5, Value1=Unknown, Value2=50V, ValueDisplayed=3.3pF
C52: library part Capacitor, "CAP, CERM, 0.6pF, 50V, NP0/C0G, +-0.1pF, 0402", Alternate Manufacturer=-, Manufacturer=Murata
C54: "CAP, CERM, 1 pF, 50 V, +/- 5%, C0G/NP0, 0402", Cap_Case=0402, Manufacturer=MuRata, Supplier Part Number 1=490-3199-1-ND, TempCo=C0G/NP0, Tolerance_%=5, Value1=Unknown, Value2=50V, ValueDisplayed=1pF
D2 D3: "Diode, Switching, 75 V, 0.3 A, SOD-523", Manufacturer="Micro Commercial Components", Supplier Part Number 1=1N4148XTPMSCT-ND, Value1=0.3A, Value2=1.25V
E1: "PCB Antenna. There is nothing to buy or mount.", Manufacturer=N/A
FID1 FID2 FID3 FID4 FID5 FID6: "Fiducial mark.  There is nothing to buy or mount.", Manufacturer=N/A
H1 H4 H6 H8: "Machine Screw, Round, #4-40 x 1/4, Nylon, Philips panhead", DigiKeyPartNumber=H542-ND, Manufacturer="B&F Fastener Supply"
H2 H3 H5 H7: "Standoff, Hex, 0.5\"L #4-40 Nylon", Manufacturer=Keystone, Supplier Part Number 1=36-1902C-ND
H9: "Lens, Ceiling Mount, TH", Manufacturer=MuRata, Supplier Part Number 1=1777666
J1 J6: "Header, 2.54 mm, 2x1, Gold, R/A, SMT", Manufacturer=Molex, Supplier Part Number 1=WM9852-ND
J2: "Header, 50mil, 5x2, Gold, TH", Manufacturer="Sullins Connector Solutions", Supplier Part Number 1=S9015E-05-ND
J3: "Header, 100mil, 2x1, Gold, TH", Manufacturer=Samtec, Supplier Part Number 1=SAM1029-02-ND
J4: "Header, 100mil, 6x1, Gold, TH", Manufacturer=Samtec, Supplier Part Number 1=SAM1029-06-ND
J5: "Jack, SMA, PCB, Gold, SMT", Manufacturer="Linx Technologies", Supplier Part Number 1=CONSMA001-SMD-G-ND
L1: "Ferrite Bead, 1500 ohm @ 100 MHz, 0.5 A, 0603", Manufacturer=MuRata, Supplier Part Number 1=490-5216-1-ND, Value1="0.5 ohm", Value2=0.5A
L2: "Inductor, Multilayer, Ferrite, 6.8 µH, 0.11 A, 0.25 ohm, SMD", Manufacturer=TDK, Supplier Part Number 1=445-6761-1-ND, Value1="0.25 ohm", Value2=0.11A, ValueDisplayed=6.8µH
L3 L5: "Inductor, Wirewound, 7.5 nH, 0.57 A, 0.13 ohm, SMD", Manufacturer=MuRata, Supplier Part Number 1=490-6846-1-ND, Value1="0.13 ohm", Value2=0.57A, ValueDisplayed=7.5nH
L4: "Inductor, Wirewound, 18 nH, 0.37 A, 0.27 ohm, SMD", Manufacturer=MuRata, Supplier Part Number 1=490-1149-1-ND, Value1="0.27 ohm", Value2=0.37A, ValueDisplayed=18nH
L6 L7: "Inductor, Wirewound, 6.8 nH, 0.7 A, 0.09 ohm, SMD", Manufacturer=MuRata, Supplier Part Number 1=490-6840-1-ND, Value1="0.09 ohm", Value2=0.7A, ValueDisplayed=6.8nH
L8: "Inductor, Wirewound, 11 nH, 0.5 A, 0.14 ohm, SMD", Manufacturer=MuRata, Supplier Part Number 1=490-6764-1-ND, Value1="0.14 ohm", Value2=0.5A, ValueDisplayed=11nH
Logo1: library part FCC_disclaimer, "FCC_disclaimer"
Logo3: library part Pb-Free
Q1: "MOSFET, P-CH, -20 V, -3.7 A, SOT-23", Alternate Manufacturer=None, Manufacturer=Vishay-Siliconix, Value1="0.031 ohm", Value2="12.5 nC"
R1: "RES, 0, 5%, 0.125 W, 0805", Manufacturer=Vishay-Dale, Power_W=0.125, Supplier Part Number 1=541-0.0ACT-ND, TempCo="200 ppm/C", Tolerance_%=5, Value1=5%, Value2=0.125W, Value_Code=0000, ValueDisplayed=0
R2: "RES, 619 k, 1%, 0.063 W, 0402", Manufacturer=Vishay-Dale, Power_W=0.063, Supplier Part Number 1=541-619KLCT-ND, TempCo="100 ppm/C", Tolerance_%=1, Value1=1%, Value2=0.063W, Value_Code=619k
R3: "RES, 6.81 k, 1%, 0.063 W, 0402", Manufacturer=Vishay-Dale, Power_W=0.063, Supplier Part Number 1=541-6.81KLCT-ND, TempCo="100 ppm/C", Tolerance_%=1, Value1=1%, Value2=0.063W, Value_Code=6k81, ValueDisplayed=6.81k
R4: "RES, 1.30 M, 1%, 0.063 W, 0402", Manufacturer=Vishay-Dale, Power_W=0.063, Supplier Part Number 1=541-1.30MLCT-ND, TempCo="100 ppm/C", Tolerance_%=1, Value1=1%, Value2=0.063W, Value_Code=1M30, ValueDisplayed=1.30M
R5: "RES, 1.50 M, 1%, 0.063 W, 0402", Manufacturer=Vishay-Dale, Power_W=0.063, Supplier Part Number 1=541-1.50MLCT-ND, TempCo="100 ppm/C", Tolerance_%=1, Value1=1%, Value2=0.063W, Value_Code=1M50, ValueDisplayed=1.50M
R6: "RES, 68.1 k, 1%, 0.063 W, 0402", Manufacturer=Vishay-Dale, Power_W=0.063, Supplier Part Number 1=541-68.1KLCT-ND, TempCo="100 ppm/C", Tolerance_%=1, Value1=1%, Value2=0.063W, Value_Code=68k1, ValueDisplayed=68.1k
R7 R8 R9 R10 R11: "RES, 15 M, 5%, 0.125 W, AEC-Q200 Grade 0, 0805", Manufacturer="Stackpole Electronics Inc", Power_W=0.125, Supplier Part Number 1=RMCF0805JT15M0CT-ND, TempCo="200 ppm/C", Tolerance_%=5, Value1=5%, Value2=0.125W, Value_Code=15M0, ValueDisplayed=15M
R12 R13: "RES, 47.5 k, 1%, 0.063 W, 0402", Manufacturer=Vishay-Dale, Power_W=0.063, Supplier Part Number 1=541-47.5KLCT-ND, TempCo="100 ppm/C", Tolerance_%=1, Value1=1%, Value2=0.063W, Value_Code=47k5, ValueDisplayed=47.5k
R14 R16 R17 R18 R19 R20: "RES, 0, 5%, 0.063 W, 0402", Manufacturer=Vishay-Dale, Power_W=0.063, Supplier Part Number 1=541-0.0JCT-ND, TempCo="200 ppm/C", Tolerance_%=5, Value1=5%, Value2=0.063W, Value_Code=0000, ValueDisplayed=0
R15: "RES, 100 k, 1%, 0.063 W, 0402", Manufacturer=Vishay-Dale, Power_W=0.063, Supplier Part Number 1=541-100KLCT-ND, TempCo="100 ppm/C", Tolerance_%=1, Value1=1%, Value2=0.063W, Value_Code=100k
S1 S2: "SWITCH TACTILE SPST-NO 0.05A 12V", CurrentRating_mA=50, Manufacturer="Omron Electronic Components", Supplier Part Number 1=SW1020CT-ND
SH-J1 SH-J3 SH-J6: "Shunt, 100mil, Gold plated, Black", Alternate Manufacturer=Samtec, Alternate PartNumber=SNT-100-BK-G, Manufacturer=3M, Supplier Part Number 1=3M9580-ND
TP1 TP2: "Test Point, Miniature, Black, TH", Manufacturer=Keystone, Supplier Part Number 1=36-5001-ND
TP6 TP7: "Test Point, Miniature, Yellow, TH", Manufacturer=Keystone, Supplier Part Number 1=36-5004-ND
TP8 TP9: "Test Point, Miniature, SMT", Manufacturer=Keystone, Supplier Part Number 1=5015KCT-ND
TP13: "Test Point, Miniature, SMT", Manufacturer=Keystone, Supplier Part Number 1=36-5015TR-ND
U2: "350 nA Rail-to-Rail I/O Nanopower Operational Amplifier Family, DGK0008A", Alternate Manufacturer="Texas Instruments", Alternate PartNumber=LPV802DGKT
U3 U4: "0.9-V to 6.5-V, Nanopower Comparator, DCK0005A", Alternate Manufacturer="Texas Instruments"
U5 U6 U7 U8: "ESD in 0402 Package with 10 pF Capacitance and 6 V Breakdown, 1 Channel, -40 to +125 degC, 2-pin X2SON (DPY), Green (RoHS & no Sb/Br)", Alternate Manufacturer="Texas Instruments", Alternate PartNumber=Equivalent, Breakdown Voltage(Min)(V)=6, IO Capacitance(Typ)(pF)=10, Supplier Part Number 1=296-30406-2-ND
U9: "Sub-1 GHz and 2.4 GHz Multi-standard RF IC Family, RGZ0048A", Alternate Manufacturer="Texas Instruments", Alternate PartNumber=CC1310F128RGZT
Y1: "Crystal, 32.768kHz, 12.5pF, SMD", Frequency=32.768KHZ, Frequency Stability=±20ppm, Manufacturer=Epson, Supplier Part Number 1=SER3672CT-ND
Y2: "Crystal, 24 MHz, 9 pF, SMD", Frequency="24 MHz", Frequency Stability=±20ppm, Manufacturer=Epson, Supplier Part Number 1=SER3634CT-ND
ZZ1 ZZ2 ZZ3 ZZ4: library part AssemblyNote, Alternate Manufacturer=-

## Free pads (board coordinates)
  round 60 hole 30: 0(410,575) 0(430,862.2) 0(468.5,466.39) 0(715,1220)

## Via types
v1: diameter 22, hole 10, Layer 1 - Top Layer to Layer 4 - Bottom Layer, tented both sides, 323 vias
v2: diameter 39.37, hole 14.96, Layer 1 - Top Layer to Layer 4 - Bottom Layer, 19 vias
v3: diameter 19.68, hole 7.87, Layer 1 - Top Layer to Layer 4 - Bottom Layer, 12 vias
v4: diameter 22, hole 10, Layer 1 - Top Layer to Layer 4 - Bottom Layer, 3 vias

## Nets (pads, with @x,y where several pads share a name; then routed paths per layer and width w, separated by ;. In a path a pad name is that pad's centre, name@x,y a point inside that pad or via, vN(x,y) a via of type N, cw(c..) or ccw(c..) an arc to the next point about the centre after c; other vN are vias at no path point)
DCDC_SW: L2.1 U9.33 | length 92.8
  Layer 1 - Top Layer w10: L2.1@1250.2,822.83 1250.2,814.8 1279.57,785.43 U9.33@1322.83,785.43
